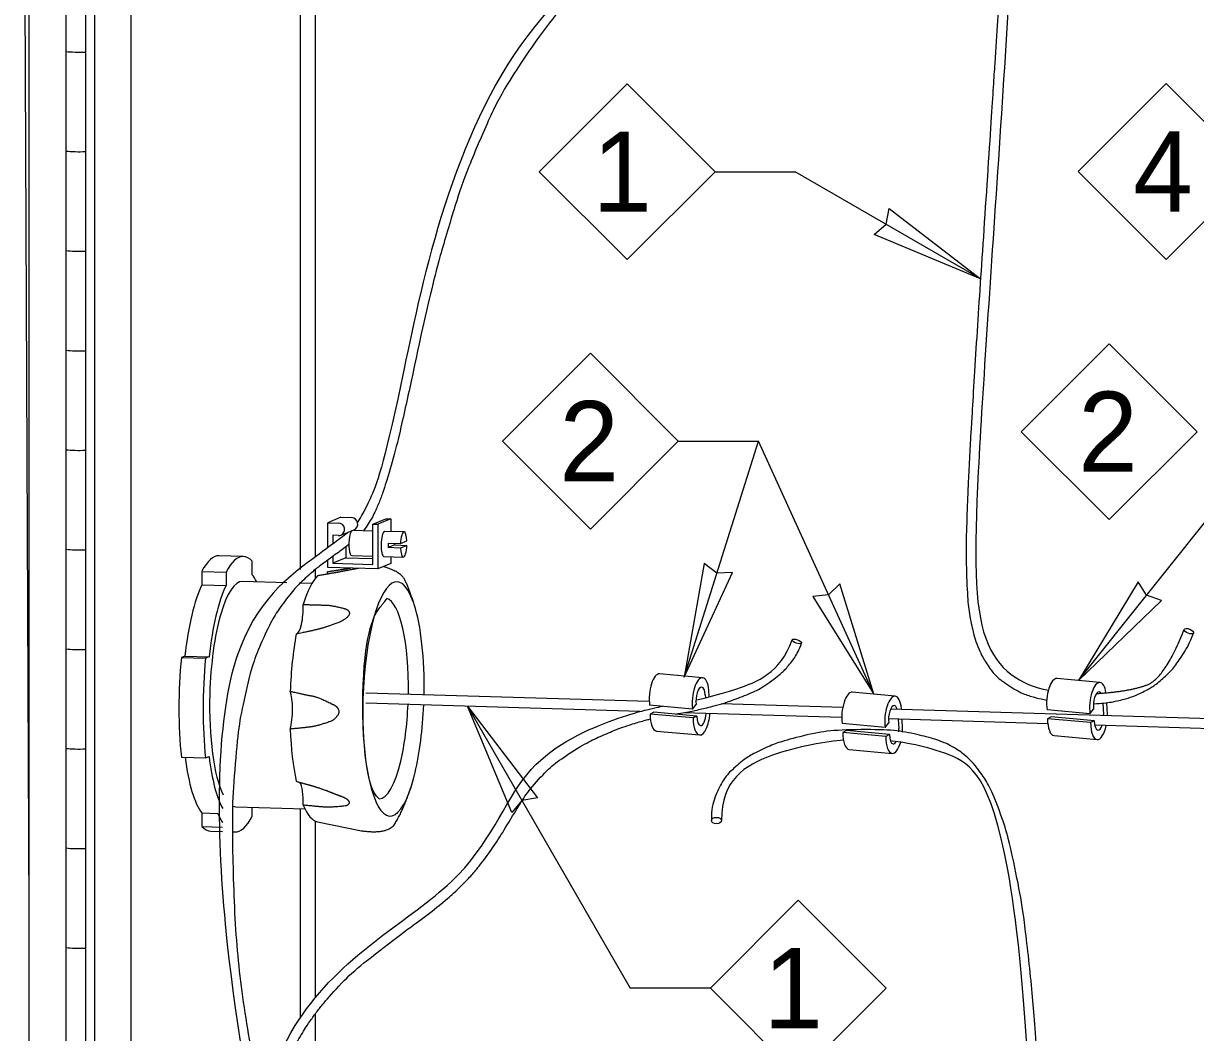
# Model space of a CAD drawing. Extents: x 99862 to 104211, y 98939 to 102076.
# Drawn here: x 102303.9 to 102537.9, y 100967.5 to 101168.9 of the extents above; entities that cross this region are included whole.
import ezdxf

# ---------------------------------------------------------------- set-up
doc = ezdxf.new("R2010")
doc.units = 0
for name, color, linetype in [('Level 1', 7, 'Continuous'), ('Level 12', 7, 'Continuous'), ('Level 15', 7, 'Continuous'), ('Level 16', 7, 'Continuous'), ('Level 20', 7, 'Continuous'), ('Level 3', 7, 'Continuous'), ('Level 30', 7, 'Continuous'), ('Level 4', 7, 'Continuous'), ('Level 5', 7, 'Continuous'), ('Level 8', 7, 'Continuous')]:
    doc.layers.add(name, color=color, linetype=linetype)

msp = doc.modelspace()

# ---------------------------------------------------------------- linework, layer by layer
at = {"layer": 'Level 1'}
for p, q in [((102316.27, 101238.88), (102316.27, 100820.74)), ((102318.11, 100820.94), (102318.11, 101238.61)), ((102325.35, 100821.83), (102325.35, 101230.69)), ((102359.12, 101200.85), (102359.12, 101059.96)), ((102362.18, 101062.49), (102362.18, 101197.78)), ((102362.18, 101058.21), (102362.18, 101059.95)), ((102359.12, 101057.19), (102359.12, 101057.19)), ((102359.12, 101012.17), (102359.12, 100970.42)), ((102362.18, 100974.53), (102362.18, 101009.7)), ((102362.18, 100911), (102362.18, 100971.29))]:
    msp.add_line(p, q, dxfattribs=at)
at = {"layer": 'Level 12'}
for p, q in [((102305, 100819.97), (102305, 101243.09)), ((102312.38, 101163.34), (102312.38, 101183.22)), ((102312.38, 101143.47), (102312.38, 101163.34)), ((102312.38, 101123.6), (102312.38, 101143.47)), ((102312.38, 101103.72), (102312.38, 101123.6)), ((102312.38, 101083.85), (102312.38, 101103.72)), ((102312.38, 101063.98), (102312.38, 101083.85)), ((102312.38, 101044.1), (102312.38, 101063.98)), ((102312.38, 101024.23), (102312.38, 101044.1)), ((102312.38, 101004.35), (102312.38, 101024.23)), ((102312.38, 100984.48), (102312.38, 101004.35)), ((102312.38, 100964.61), (102312.38, 100984.48))]:
    msp.add_line(p, q, dxfattribs=at)
for centre, major_axis, start_param, end_param in [((102315.06, 101163.63), (-3.72, 0), 0.768587, 1.900509), ((102315.06, 101143.76), (3.72, 0), 3.910179, 5.042102), ((102315.06, 101123.89), (-3.72, 0), 0.768587, 1.900509), ((102315.06, 101104.01), (3.72, 0), 3.910179, 5.042102), ((102315.06, 101084.14), (-3.72, 0), 0.768587, 1.900509), ((102315.06, 101064.27), (3.72, 0), 3.910179, 5.042102), ((102315.06, 101044.39), (-3.72, 0), 0.768587, 1.900509), ((102315.06, 101024.52), (3.72, 0), 3.910179, 5.042102), ((102315.06, 101004.64), (-3.72, 0), 0.768587, 1.900509), ((102315.06, 100984.77), (3.72, 0), 3.910179, 5.042102)]:
    msp.add_ellipse(centre, major_axis=major_axis, ratio=0.112235, start_param=start_param, end_param=end_param, dxfattribs=at)
at = {"layer": 'Level 15'}
for p, q in [((102441.96, 101139.35), (102457.96, 101139.35)), ((102494.97, 101117.98), (102457.96, 101139.35)), ((102514.53, 101037.79), (102554.21, 101087.44)), ((102434.61, 101085.57), (102450.61, 101085.57)), ((102435.77, 101038.45), (102450.6, 101085.57)), ((102473.63, 101035.04), (102450.61, 101085.57)), ((102392.52, 101032.66), (102425.02, 100976.37)), ((102441.02, 100976.37), (102425.02, 100976.37))]:
    msp.add_line(p, q, dxfattribs=at)
for points in [[(102494.97, 101117.98), (102473.71, 101126.81), (102476.12, 101128.87), (102476.69, 101131.98)], [(102435.77, 101038.45), (102445.47, 101059.33), (102442.31, 101059.22), (102439.78, 101061.12)], [(102473.63, 101035.04), (102466.88, 101057.06), (102464.6, 101054.86), (102461.45, 101054.58)], [(102514.53, 101037.79), (102531.11, 101053.76), (102528.12, 101054.8), (102526.45, 101057.49)], [(102392.52, 101032.66), (102406.52, 101014.38), (102403.41, 101013.81), (102401.35, 101011.4)]]:
    msp.add_lwpolyline(points, close=True, dxfattribs=at)
at = {"layer": 'Level 16'}
for p, q in [((102439.47, 101038.32), (102430.89, 101039.12)), ((102518.82, 101037.39), (102510.23, 101038.18)), ((102440.8, 101034.53), (102440.72, 101035.87)), ((102477.92, 101034.65), (102469.33, 101035.44)), ((102437.48, 101032.09), (102428.89, 101032.89)), ((102437.48, 101032.09), (102438.2, 101033)), ((102440, 101035), (102440.04, 101034.33)), ((102519.4, 101033.27), (102519.54, 101030.97)), ((102520.31, 101031.01), (102520.17, 101033.36)), ((102429.75, 101031.46), (102429, 101031.09)), ((102437.58, 101030.3), (102429, 101031.09)), ((102438.34, 101030.67), (102429.75, 101031.46)), ((102438.34, 101030.67), (102437.58, 101030.3)), ((102479.18, 101032.02), (102479.17, 101032.2)), ((102516.82, 101031.16), (102508.24, 101031.95)), ((102509.1, 101030.53), (102508.35, 101030.16)), ((102517.69, 101029.73), (102509.1, 101030.53)), ((102516.82, 101031.16), (102517.54, 101032.07)), ((102475.93, 101028.42), (102467.34, 101029.21)), ((102475.93, 101028.42), (102476.65, 101029.32)), ((102478.53, 101030.04), (102478.64, 101028.23)), ((102479.41, 101028.26), (102479.3, 101030.02)), ((102516.93, 101029.37), (102508.35, 101030.16)), ((102517.69, 101029.73), (102516.93, 101029.37)), ((102430.3, 101027.7), (102438.88, 101026.91)), ((102468.2, 101027.78), (102467.45, 101027.41)), ((102476.03, 101026.62), (102467.45, 101027.41)), ((102476.79, 101026.99), (102468.2, 101027.78)), ((102476.79, 101026.99), (102476.03, 101026.62)), ((102509.65, 101026.77), (102518.23, 101025.98)), ((102468.75, 101024.03), (102477.33, 101023.23))]:
    msp.add_line(p, q, dxfattribs=at)
for centre, major_axis, start_param, end_param in [((102430.5, 101034.91), (0.39, 4.21), 0, 2.107327), ((102439.08, 101034.12), (0.39, 4.21), 0, 2.107327), ((102439.08, 101034.12), (0.39, 4.21), 5.178942, 6.283185), ((102509.85, 101033.97), (0.39, 4.21), 0, 2.107327), ((102439.08, 101034.12), (-0.21, -2.33), 3.141593, 5.248919), ((102439.08, 101034.12), (-0.21, -2.33), 1.93234, 3.141593), ((102468.95, 101031.23), (0.39, 4.21), 0, 2.107327), ((102518.43, 101033.18), (0.39, 4.21), 0, 2.107327), ((102518.43, 101033.18), (-0.21, -2.33), 3.141593, 5.248919), ((102518.43, 101033.18), (-0.21, -2.33), 2.698084, 3.141593), ((102518.43, 101033.18), (0.39, 4.21), 5.291536, 6.283185), ((102477.53, 101030.44), (0.39, 4.21), 0, 2.107327), ((102477.53, 101030.44), (-0.21, -2.33), 3.141593, 5.248919), ((102477.53, 101030.44), (0.39, 4.21), 5.178942, 6.283185), ((102430.68, 101031.91), (0.39, 4.21), 1.802895, 3.141593), ((102439.27, 101031.12), (-0.21, -2.33), 4.944488, 6.283185), ((102439.27, 101031.12), (0.39, 4.21), 3.141593, 4.764209), ((102439.27, 101031.12), (-0.21, -2.33), 0, 1.64517), ((102477.53, 101030.44), (-0.21, -2.33), 2.372706, 3.141593), ((102518.62, 101030.19), (-0.21, -2.33), 1.870938, 1.949891), ((102518.62, 101030.19), (0.39, 4.21), 4.887592, 4.944488), ((102439.27, 101031.12), (0.39, 4.21), 1.802895, 3.141593), ((102477.72, 101027.44), (-0.21, -2.33), 1.660417, 1.949891), ((102477.72, 101027.44), (0.39, 4.21), 4.754701, 4.944488), ((102510.03, 101030.98), (0.39, 4.21), 1.802895, 3.141593), ((102518.62, 101030.19), (0.39, 4.21), 1.802895, 3.141593), ((102518.62, 101030.19), (-0.21, -2.33), 4.944488, 6.283185), ((102518.62, 101030.19), (0.39, 4.21), 3.141593, 4.4072), ((102518.62, 101030.19), (-0.21, -2.33), 0, 0.969755), ((102469.13, 101028.23), (0.39, 4.21), 1.802895, 3.141593), ((102477.72, 101027.44), (0.39, 4.21), 1.802895, 3.141593), ((102477.72, 101027.44), (-0.21, -2.33), 4.944488, 6.283185), ((102477.72, 101027.44), (0.39, 4.21), 3.141593, 4.268139), ((102477.72, 101027.44), (-0.21, -2.33), 0, 0.702155)]:
    msp.add_ellipse(centre, major_axis=major_axis, ratio=0.389923, start_param=start_param, end_param=end_param, dxfattribs=at)
at = {"layer": 'Level 20'}
for points in [[(102424.41, 101156.9), (102441.96, 101139.35), (102424.41, 101121.8), (102406.86, 101139.35)], [(102532.02, 101156.93), (102549.57, 101139.38), (102532.02, 101121.82), (102514.47, 101139.38)], [(102417.06, 101103.12), (102434.61, 101085.57), (102417.06, 101068.02), (102399.51, 101085.57)], [(102520.66, 101104.99), (102538.21, 101087.44), (102520.66, 101069.89), (102503.1, 101087.44)], [(102458.58, 100993.92), (102476.13, 100976.37), (102458.58, 100958.82), (102441.02, 100976.37)]]:
    msp.add_lwpolyline(points, close=True, dxfattribs=at)
at = {"layer": 'Level 3'}
msp.add_line((102305, 100991.25), (102303.87, 101242.9), dxfattribs=at)
at = {"layer": 'Level 30'}
for p, q in [((102428.82, 101033.56), (102372.26, 101035.28)), ((102426.91, 101031.61), (102372.22, 101033.28)), ((102467.45, 101032.38), (102443.19, 101033.12)), ((102467.26, 101030.39), (102435.56, 101031.35)), ((102643.49, 101027.02), (102477.02, 101032.09)), ((102508.4, 101029.13), (102476.6, 101030.1)), ((102582.44, 101026.88), (102517.77, 101028.85))]:
    msp.add_line(p, q, dxfattribs=at)
for centre, major_axis, ratio in [((102536.57, 101047.62), (-0.93, 0.368), 0.4341), ((102458.29, 101045.58), (-0.945, 0.326), 0.361081), ((102442.23, 101009.81), (-1, 0), 0.654359)]:
    msp.add_ellipse(centre, major_axis=major_axis, ratio=ratio, dxfattribs=at)
for points, degree in [([(102492.15, 101215.46), (102490.81, 101215.29), (102482.9, 101214.1), (102460.41, 101208.52), (102393.4, 101170.91), (102377.25, 101084.36), (102372.86, 101072.92), (102370.82, 101069.79), (102370.54, 101069.4)], 3), ([(102653.5, 101080.61), (102648.82, 101143.1), (102596.56, 101184.64), (102512.98, 101213.37), (102506.37, 101215.18), (102502.55, 101215.62), (102502.45, 101215.64)], 3), ([(102492.38, 101213.47), (102491.09, 101213.31), (102489.67, 101213.1), (102484.6, 101212.21), (102480.39, 101211.29), (102469.68, 101207.9), (102463.18, 101205.42), (102447.09, 101197.96), (102437.56, 101193), (102419.16, 101179.88), (102410.3, 101171.73), (102400.16, 101156.6), (102397.28, 101151.02), (102392.33, 101139.44), (102390.27, 101133.43), (102386.76, 101121.61), (102385.31, 101115.8), (102382.84, 101104.99), (102381.81, 101099.99), (102379.02, 101087.14), (102377.57, 101081.49), (102375.73, 101075.59), (102375.17, 101074.04), (102374.11, 101071.5), (102373.6, 101070.51), (102372.66, 101068.93), (102372.22, 101068.27), (102371.74, 101067.68)], 3), ([(102652.41, 101059.13), (102651.5, 101080.89), (102649.81, 101096.71), (102643.91, 101122.9), (102639.7, 101133.26), (102629.63, 101150.15), (102623.77, 101156.69), (102611.07, 101167.56), (102604.24, 101171.89), (102583.43, 101183.84), (102569.35, 101190.28), (102544.15, 101200.52), (102533.03, 101204.31), (102517.07, 101209.68), (102512.28, 101211.24), (102507.45, 101212.64), (102506.24, 101212.95), (102504.21, 101213.38), (102503.39, 101213.51), (102502.46, 101213.62), (102502.41, 101213.63), (102502.36, 101213.63)], 3), ([(102502.44, 101205.65), (102501.86, 101194.2), (102498.75, 101142.75), (102493.68, 101073.03), (102493.68, 101042.56), (102502.95, 101036.94), (102508.51, 101035.84)], 3), ([(102500.29, 101202.72), (102499.91, 101195.44), (102499.52, 101188.73), (102498.94, 101179.16), (102498.75, 101176.05), (102498.36, 101169.93), (102497.79, 101160.9), (102497.24, 101152.33), (102495.44, 101124.86), (102494.17, 101106.31), (102493.07, 101087.93), (102492.88, 101084.5), (102492.55, 101078.11), (102492.41, 101075.16), (102492.11, 101066.96), (102492.05, 101062.36), (102492.32, 101054.5), (102492.66, 101051.24), (102493.58, 101047.04), (102493.96, 101045.76), (102494.89, 101043.4), (102495.44, 101042.31), (102497.35, 101039.36), (102498.96, 101037.8), (102502.69, 101035.44), (102504.79, 101034.64), (102507.43, 101034.02), (102507.8, 101033.94), (102508.18, 101033.86)], 3), ([(102368.73, 101067.42), (102367.47, 101066.31), (102362.78, 101063.12), (102342.34, 101047.18), (102342.34, 100988.77), (102349.57, 100951.62), (102350.1, 100949.04)], 3), ([(102368.84, 101064.92), (102367.67, 101064.01), (102366.28, 101063.04), (102363.21, 101060.77), (102361.87, 101059.76), (102359.05, 101057.2), (102357.56, 101055.64), (102354.62, 101051.71), (102353.17, 101049.33), (102350.5, 101043.45), (102349.29, 101039.96), (102347.33, 101031.59), (102346.59, 101026.69), (102345.67, 101015.66), (102345.49, 101009.52), (102345.91, 100989.52), (102347.46, 100974.04), (102350.8, 100955.82), (102351.04, 100954.57), (102351.28, 100953.32)], 3), ([(102517.52, 101033.15), (102519.23, 101033.21), (102521.01, 101033.41), (102524.22, 101034.17), (102525.65, 101034.66), (102528.46, 101036), (102529.82, 101036.86), (102532.38, 101039.03), (102533.58, 101040.33), (102535.73, 101043.42), (102536.69, 101045.2), (102537.5, 101047.25)], 3), ([(102518.12, 101035.18), (102524.77, 101035.58), (102531.79, 101038.28), (102535.64, 101047.99)], 2), ([(102433.97, 101031.07), (102435.58, 101031.35), (102437.25, 101031.64), (102440.19, 101032.3), (102441.32, 101032.58), (102443.74, 101033.27), (102445.02, 101033.68), (102448.92, 101035.15), (102451.59, 101036.43), (102455.07, 101039.11), (102456.14, 101040.12), (102457.97, 101042.46), (102458.73, 101043.78), (102459.24, 101045.26)], 3), ([(102438.16, 101033.9), (102439.01, 101034.08), (102445.53, 101035.61), (102455.05, 101039.26), (102457.35, 101045.91)], 3), ([(102347.06, 100923.18), (102347.06, 100940.63), (102354.92, 100976.77), (102394.55, 100996.78), (102402.33, 101021.61), (102422.33, 101030.68), (102429.5, 101032.28), (102431.46, 101032.65)], 3), ([(102349.06, 100922.95), (102349.09, 100929.93), (102349.63, 100936.29), (102351.84, 100948.65), (102353.54, 100954.65), (102356.98, 100962.74), (102358.27, 100965.29), (102360.44, 100968.82), (102361.19, 100969.95), (102362.78, 100972.11), (102363.62, 100973.15), (102367.95, 100978.14), (102371.91, 100981.51), (102379.85, 100987.66), (102383.83, 100990.42), (102388.18, 100993.97), (102389.03, 100994.68), (102390.63, 100996.13), (102391.39, 100996.87), (102393.53, 100999.1), (102394.78, 101000.6), (102398.15, 101005.09), (102399.88, 101008.04), (102403.2, 101013.46), (102404.79, 101015.93), (102408.59, 101020.12), (102410.9, 101021.96), (102415.84, 101025.11), (102418.46, 101026.41), (102422.18, 101027.96), (102423.4, 101028.41), (102425.68, 101029.18), (102426.74, 101029.5), (102428.19, 101029.89), (102428.62, 101029.99), (102429.05, 101030.1)], 3), ([(102508.73, 100842.53), (102508.69, 100894.86), (102507.98, 100928.83), (102506.19, 100964.86), (102505.45, 100974.41), (102503.77, 100989.8), (102502.83, 100995.65), (102500.79, 101005.4), (102499.68, 101009.32), (102497.25, 101015.71), (102495.91, 101018.2), (102493.64, 101021.13), (102492.85, 101021.98), (102491.17, 101023.43), (102490.29, 101024.03), (102488.49, 101025.05), (102487.57, 101025.45), (102485.69, 101026.13), (102484.73, 101026.4), (102479.9, 101027.58), (102475.54, 101028.04), (102466.6, 101027.95), (102462.03, 101027.4), (102455.62, 101025.73), (102453.55, 101025.03), (102449.7, 101023.26), (102447.92, 101022.18), (102444.83, 101019.53), (102443.53, 101017.95), (102441.73, 101014.24), (102441.23, 101012.13), (102441.23, 101009.81)], 3), ([(102467.58, 101025.85), (102464.41, 101025.62), (102452.58, 101023.78), (102443.23, 101017.96), (102443.23, 101009.81)], 3), ([(102506.74, 100842.51), (102506.64, 100947.24), (102500.92, 101015.8), (102489.24, 101023.86), (102479.19, 101025.53), (102476.96, 101025.74)], 3)]:
    msp.add_open_spline(points, degree=degree, dxfattribs=at)
at = {"layer": 'Level 4'}
for p, q in [((102347.77, 101062.54), (102342.94, 101062.68)), ((102349.55, 101058.9), (102349.55, 101061.59)), ((102339.49, 101059.57), (102344.31, 101059.42)), ((102339.49, 101059.57), (102339.49, 101056.88)), ((102344.31, 101059.42), (102344.31, 101056.73)), ((102339.49, 101056.88), (102344.31, 101056.73)), ((102356.45, 101057.27), (102347.62, 101057.54)), ((102361.45, 101057.12), (102359.11, 101057.19)), ((102336.11, 101042.65), (102335.4, 101042.36)), ((102335.4, 101042.36), (102340.23, 101042.21)), ((102336.11, 101042.65), (102340.93, 101042.5)), ((102340.93, 101042.5), (102340.23, 101042.21)), ((102335.4, 101022.49), (102340.23, 101022.34)), ((102340.23, 101022.34), (102340.93, 101022.63)), ((102346.25, 101012.56), (102360.08, 101012.14)), ((102349.55, 101010.68), (102349.55, 101012.46)), ((102339.49, 101011.35), (102339.49, 101008.66)), ((102339.49, 101011.35), (102342.68, 101011.25)), ((102339.49, 101008.66), (102343.59, 101008.53)), ((102341.27, 101007.71), (102343.58, 101007.64)), ((102345.58, 101007.58), (102346.09, 101007.56))]:
    msp.add_line(p, q, dxfattribs=at)
for centre, major_axis, start_param, end_param in [((102342.11, 101035.2), (0.84, 27.49), 0, 0.488668), ((102346.93, 101035.05), (0.84, 27.49), 0, 0.488668), ((102346.93, 101035.05), (0.84, 27.49), 6.027517, 6.283185), ((102346.93, 101035.05), (0.76, 24.99), 5.832158, 5.988168), ((102342.11, 101035.2), (0.76, 24.99), 0.528017, 1.275779), ((102346.93, 101035.05), (0.76, 24.99), 0.528017, 1.275779), ((102346.93, 101035.05), (-0.68, -22.49), 3.141593, 4.720308), ((102342.11, 101035.2), (0.84, 27.49), 1.315128, 2.059465), ((102346.93, 101035.05), (0.84, 27.49), 1.315128, 2.059465), ((102346.93, 101035.05), (-0.68, -22.49), 4.720308, 5.826995), ((102342.11, 101035.2), (0.76, 24.99), 2.113433, 2.846576), ((102346.93, 101035.05), (0.76, 24.99), 2.098813, 2.732329), ((102346.93, 101035.05), (-0.68, -22.49), 6.182332, 6.283185), ((102346.93, 101035.05), (0.84, 27.49), 2.625625, 2.776265), ((102346.93, 101035.05), (0.84, 27.49), 3.141593, 3.630261), ((102342.11, 101035.2), (0.84, 27.49), 2.885924, 3.141593), ((102346.93, 101035.05), (0.84, 27.49), 3.069697, 3.141593)]:
    msp.add_ellipse(centre, major_axis=major_axis, ratio=0.260126, start_param=start_param, end_param=end_param, dxfattribs=at)
at = {"layer": 'Level 5'}
for p, q in [((102359.56, 101047.32), (102358.32, 101047.05)), ((102380.73, 101015.01), (102380.91, 101015.48)), ((102362.55, 101009.59), (102371.34, 101007.79))]:
    msp.add_line(p, q, dxfattribs=at)
for centre, major_axis, ratio, start_param, end_param in [((102363.6, 101034.54), (0.76, 24.99), 0.260126, 0.26897, 0.749428), ((102363.6, 101062.53), (-0.14, -5.31), 0.245065, 0.852697, 0.97113), ((102377.75, 101034.11), (-0.71, -23.39), 0.260126, 2.582287, 4.043491), ((102375.5, 101034.18), (0.61, 19.99), 0.260126, 4.76241, 6.228982), ((102358.38, 101052.18), (0.07, 5.12), 0.263287, 3.202864, 4.871482), ((102377.75, 101034.11), (-0.71, -23.39), 0.260126, 2.516371, 2.582287), ((102377.75, 101034.11), (-0.71, -23.39), 0.260126, 1.61354, 2.516371), ((102363.6, 101034.54), (0.76, 24.99), 0.260126, 1.054368, 1.534826), ((102377.75, 101034.11), (-0.71, -23.39), 0.260126, 4.043491, 7.128446), ((102356.22, 101031.49), (0.17, 5), 0.276051, 3.974942, 5.699725), ((102375.5, 101034.18), (0.61, 19.99), 0.260126, 4.043491, 4.662368), ((102377.75, 101034.11), (-0.71, -23.39), 0.260126, 0.900877, 1.528052), ((102363.6, 101034.54), (0.76, 24.99), 0.260126, 1.839766, 2.320224), ((102375.5, 101034.18), (0.61, 19.99), 0.260126, 3.146469, 4.043491), ((102377.75, 101034.11), (-0.71, -23.39), 0.260126, 0.871418, 0.900877), ((102358.38, 101012.59), (0.24, 5.19), 0.255964, 4.785615, 5.936876), ((102363.6, 101034.54), (0.76, 24.99), 0.260126, 2.625164, 3.096677)]:
    msp.add_ellipse(centre, major_axis=major_axis, ratio=ratio, start_param=start_param, end_param=end_param, dxfattribs=at)
for points, degree in [([(102370.77, 101060.16), (102368.04, 101059.64), (102365.31, 101059.15), (102362.6, 101058.69)], 2), ([(102364.59, 101059.51), (102366.13, 101059.75), (102367.66, 101059.98), (102369.14, 101060.21)], 2), ([(102381.82, 101053.22), (102380.83, 101056.22), (102379.22, 101059.49), (102375.75, 101060.51)], 2), ([(102374.92, 101014.19), (102371.67, 101016.1), (102370.75, 101047.44), (102376.39, 101053.9), (102376.42, 101054.23), (102376.49, 101054.24), (102376.5, 101054.25)], 3), ([(102359.73, 101052.97), (102362.51, 101052.85), (102365.38, 101052.84), (102367.87, 101052.16)], 2), ([(102367.87, 101052.16), (102368.89, 101051.93), (102369.01, 101050.54), (102367.24, 101049.53)], 2), ([(102367.24, 101049.53), (102364.73, 101048.57), (102362.19, 101047.84), (102359.65, 101047.34)], 2), ([(102357.13, 101035.64), (102359.96, 101034.98), (102362.85, 101034.44), (102365.53, 101033.08)], 2), ([(102365.53, 101033.08), (102366.61, 101032.63), (102367.05, 101030.94), (102365.53, 101029.73)], 2), ([(102365.53, 101029.73), (102362.82, 101028.76), (102359.99, 101028.33), (102357.13, 101028.09)], 2), ([(102380.91, 101015.48), (102381.26, 101016.41), (102381.56, 101017.47), (102381.95, 101018.91)], 2), ([(102358.32, 101017.66), (102360.3, 101017.11), (102362.27, 101016.55), (102364.25, 101015.86)], 2), ([(102364.25, 101015.86), (102365.24, 101015.47), (102366.24, 101015.08), (102367.24, 101014.7)], 2), ([(102367.24, 101014.7), (102368.41, 101014.28), (102369.16, 101013.26), (102368.38, 101012.77)], 2), ([(102371.3, 101007.8), (102376.67, 101007.03), (102379.37, 101011.3), (102380.73, 101015.01)], 2), ([(102368.38, 101012.77), (102365.33, 101012.42), (102362.56, 101012.6), (102359.73, 101012.91)], 2)]:
    msp.add_open_spline(points, degree=degree, dxfattribs=at)
at = {"layer": 'Level 8'}
for p, q in [((102367.23, 101070.36), (102364.61, 101069.27)), ((102367.23, 101070.36), (102369.4, 101070.29)), ((102364.61, 101069.27), (102366.78, 101069.21)), ((102364.61, 101064.28), (102364.61, 101069.27)), ((102373.61, 101069), (102376.23, 101070.08)), ((102373.61, 101069), (102374.61, 101068.97)), ((102373.61, 101060.97), (102373.61, 101069)), ((102377.23, 101070.05), (102374.61, 101068.97)), ((102374.61, 101068.97), (102374.61, 101060.04)), ((102376.23, 101070.08), (102377.23, 101070.05)), ((102377.23, 101070.05), (102377.23, 101067.51)), ((102366.78, 101066.72), (102365.61, 101066.76)), ((102365.61, 101066.76), (102365.61, 101065.01)), ((102367.26, 101066.81), (102369.87, 101067.89)), ((102368.23, 101067.21), (102368.23, 101066.99)), ((102373.61, 101067.62), (102369.57, 101067.74)), ((102379.85, 101067.43), (102376, 101067.55)), ((102379.13, 101065.1), (102380.42, 101065.64)), ((102368.23, 101064.45), (102368.23, 101062.29)), ((102376.72, 101065.18), (102379.13, 101065.1)), ((102378.01, 101064.83), (102376.72, 101064.3)), ((102379.13, 101064.23), (102376.72, 101064.3)), ((102378.01, 101064.83), (102380.42, 101064.76)), ((102380.42, 101064.76), (102379.13, 101064.23)), ((102364.61, 101060.35), (102364.61, 101061.81)), ((102365.61, 101062.54), (102365.61, 101061.21)), ((102368.23, 101062.29), (102365.61, 101061.21)), ((102365.61, 101061.21), (102373.61, 101060.97)), ((102368.23, 101062.29), (102373.61, 101062.13)), ((102369.41, 101062.74), (102373.61, 101062.62)), ((102377.23, 101061.13), (102374.61, 101060.04)), ((102375.84, 101062.55), (102379.7, 101062.43)), ((102377.23, 101062.51), (102377.23, 101061.13)), ((102374.61, 101060.04), (102364.61, 101060.35))]:
    msp.add_line(p, q, dxfattribs=at)
for centre, major_axis, ratio, start_param, end_param in [((102369.4, 101069.05), (-0.48, 1.16), 0.959029, 3.141593, 5.875853), ((102366.78, 101067.97), (-0.48, 1.16), 0.959029, 3.141593, 5.875853), ((102366.78, 101067.97), (-0.48, 1.16), 0.959029, 2.734261, 3.141593), ((102369.49, 101065.24), (0.08, 2.5), 0.260126, 6.283185, 9.424778), ((102375.92, 101065.05), (0.08, 2.5), 0.260126, 0.1165, 3.141593), ((102375.92, 101065.05), (0.08, 2.5), 0.260126, 0, 0.1165), ((102379.78, 101064.93), (0.08, 2.5), 0.260126, 6.283185, 7.793174), ((102379.78, 101064.93), (0.08, 2.5), 0.260126, 5.006196, 6.283185), ((102377.36, 101065), (0.08, 2.5), 0.260126, 1.509989, 1.864603), ((102377.36, 101065), (0.08, 2.5), 0.260126, 4.651582, 4.773196), ((102379.78, 101064.93), (0.08, 2.5), 0.260126, 1.864603, 3.141593), ((102379.78, 101064.93), (0.08, 2.5), 0.260126, 3.141593, 4.651582)]:
    msp.add_ellipse(centre, major_axis=major_axis, ratio=ratio, start_param=start_param, end_param=end_param, dxfattribs=at)

# ---------------------------------------------------------------- texts
at = {"layer": 'Level 20'}
for s, p in [('1', (102417.46, 101131.35)), ('4', (102525.43, 101131.38)), ('2', (102410.88, 101077.57)), ('2', (102514.48, 101079.44)), ('1', (102451.62, 100968.37))]:
    msp.add_text(s, height=16, dxfattribs=at).set_placement(p)

doc.saveas('drawing.dxf')
